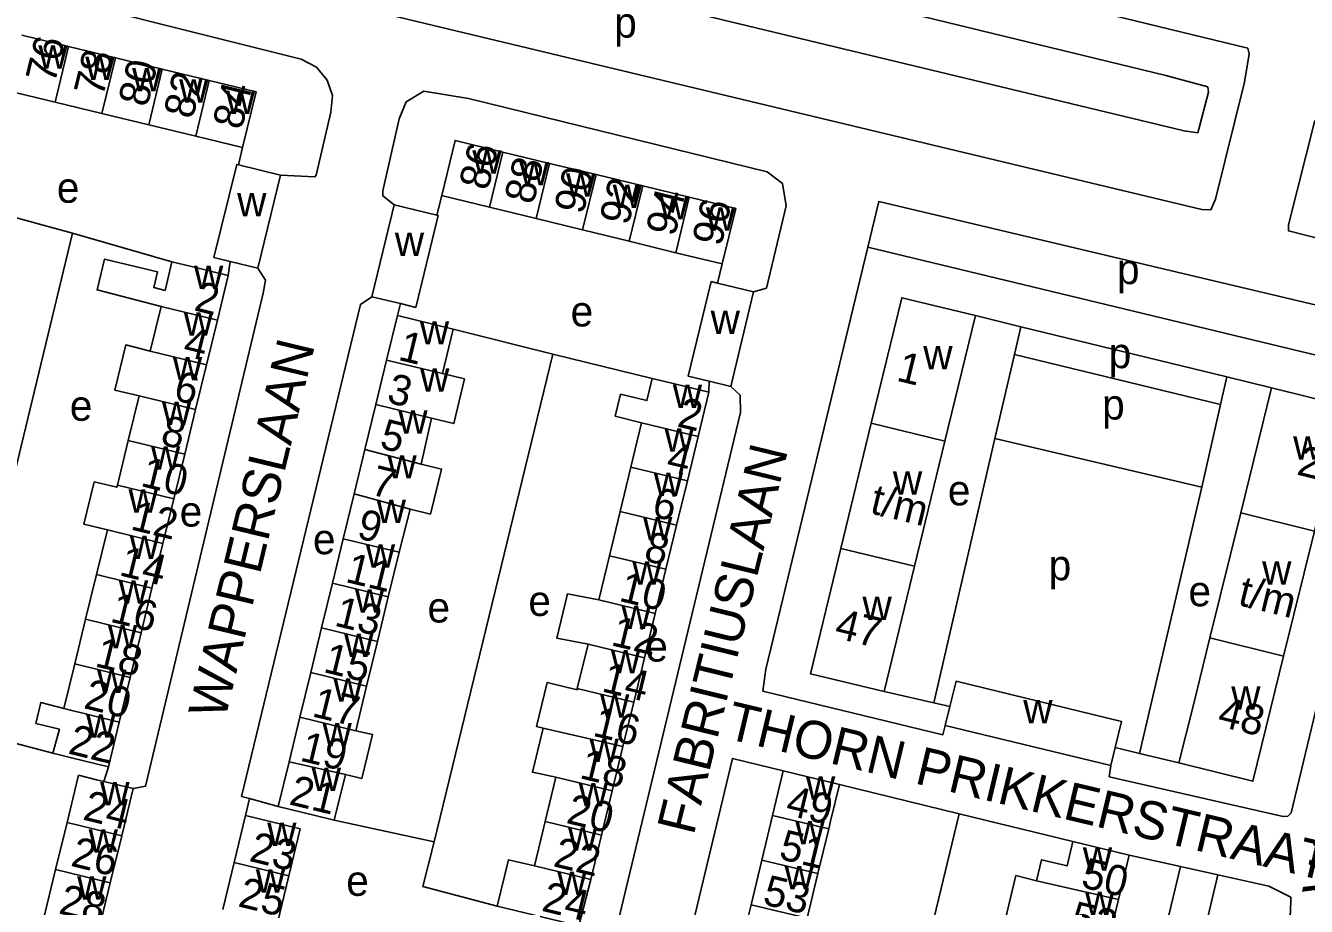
# Model space of a CAD drawing. Extents: x 162804 to 165059, y 381530 to 382901.
# Drawn here: x 163597.8 to 163766.6, y 382106.1 to 382222.2 of the extents above; entities that cross this region are included whole.
import ezdxf

# ---------------------------------------------------------------- set-up
doc = ezdxf.new("R2010")
doc.units = 0
for name, color, linetype in [('BLT_Basislijn', 7, 'Continuous'), ('BLT_Bebouwing', 7, 'Continuous'), ('BLT_Centroide', 7, 'Continuous'), ('BLT_Huisnummer', 7, 'Continuous'), ('BLT_Huisnummer_ tussenligend', 7, 'Continuous'), ('BLT_Huisnummer_reeks', 7, 'Continuous'), ('BLT_Onderverdeling_panden', 7, 'Continuous'), ('BLT_Straatnaam', 7, 'Continuous')]:
    doc.layers.add(name, color=color, linetype=linetype)

msp = doc.modelspace()

# ---------------------------------------------------------------- linework, layer by layer
at = {"layer": 'BLT_Basislijn'}
for p, q in [((163625.89, 382203.82), (163626.42, 382206.12)), ((163652.03, 382197.22), (163652.67, 382199.79)), ((163591.17, 382198.33), (163604.02, 382194.84)), ((163604.02, 382194.84), (163617.1, 382191.06)), ((163708.82, 382193), (163776.35, 382176.69)), ((163624.78, 382191.1), (163624.54, 382189.24)), ((163689.02, 382188.24), (163689.64, 382190.77)), ((163646.82, 382183.99), (163647.21, 382185.55)), ((163729, 382182.49), (163722.99, 382183.96)), ((163667.3, 382178.87), (163654.17, 382182.2)), ((163729, 382182.49), (163728.13, 382178.85)), ((163756.13, 382175.88), (163729, 382182.49)), ((163667.3, 382178.87), (163651.65, 382114.63)), ((163680.41, 382175.69), (163667.3, 382178.87)), ((163725.53, 382167.77), (163728.13, 382178.85)), ((163728.13, 382178.85), (163755.31, 382172.24)), ((163687.85, 382173.89), (163687.91, 382175.32)), ((163755.31, 382172.24), (163756.13, 382175.88)), ((163762.03, 382174.44), (163756.13, 382175.88)), ((163752.81, 382161.36), (163755.31, 382172.24)), ((163725.53, 382167.77), (163717.53, 382132.92)), ((163725.53, 382167.77), (163752.81, 382161.36)), ((163752.81, 382161.36), (163744.6, 382126.26)), ((163717.53, 382132.92), (163710.96, 382134.41)), ((163719.62, 382132.44), (163717.53, 382132.92)), ((163601.42, 382126.29), (163588.25, 382129.72)), ((163744.6, 382126.26), (163741.39, 382127.03)), ((163749.81, 382125.01), (163744.6, 382126.26)), ((163608.13, 382122.58), (163608.74, 382124.5)), ((163705.08, 382122.19), (163720.87, 382118.32)), ((163626.82, 382118.07), (163627.33, 382120.31)), ((163631.13, 382119.27), (163627.33, 382120.31)), ((163720.87, 382118.32), (163735.85, 382114.65)), ((163651.65, 382114.63), (163638.48, 382117.49)), ((163743.26, 382112.86), (163750.03, 382111.37)), ((163750.03, 382111.37), (163754.92, 382110.28)), ((163754.92, 382110.28), (163732.81, 382015.31))]:
    msp.add_line(p, q, dxfattribs=at)
for points in [[(163535.81, 382273.16), (163541.5, 382271.99), (163758.91, 382219.21), (163759.07, 382218.46), (163758.45, 382214.75), (163754.63, 382199.3), (163754.03, 382197.92), (163752.81, 382197.95), (163531.23, 382251.04)], [(163534.57, 382267.49), (163748.1, 382215.63), (163753.62, 382214.11), (163753.7, 382213.43), (163752.3, 382208.06), (163750.49, 382208.3), (163532.9, 382260.7)], [(163584.4, 382214.48), (163582.73, 382215.55), (163583.19, 382218.74), (163585.18, 382225.87), (163587.83, 382228.45), (163591.81, 382228.37), (163634.14, 382217.78), (163636.14, 382216.71), (163637.58, 382214.99), (163638.26, 382212.97), (163638.03, 382210.78), (163636.11, 382202.48), (163635.95, 382202.25), (163631.41, 382202.47)], [(163646.4, 382198.58), (163644.88, 382199.75), (163644.88, 382200.39), (163647.04, 382209.91), (163647.99, 382212.14), (163650.32, 382213.56), (163656.2, 382212.59), (163695.54, 382202.93), (163697.55, 382201.39), (163698.04, 382198.44), (163695.45, 382187.58), (163693.75, 382187.1)], [(163767.73, 382209.7), (163764.26, 382195.93), (163764.26, 382195.13), (163784.61, 382189.94)], [(163708.82, 382193), (163710.26, 382198.99), (163771.27, 382184.56), (163774.28, 382183.7), (163774.6, 382183.28), (163776.2, 382178.16), (163776.35, 382176.69)], [(163604.02, 382194.84), (163588.41, 382130.31), (163588.25, 382129.72)], [(163719.02, 382129.96), (163718.7, 382128.72), (163694.97, 382134.49), (163695.39, 382137.36), (163708.82, 382193)], [(163612.01, 382121.63), (163613.61, 382121.94), (163614.17, 382124.15), (163629.13, 382186.91), (163629.46, 382188.63), (163628.42, 382190.21)], [(163627.33, 382120.31), (163626.28, 382120.6), (163641.94, 382185.45), (163643.46, 382186.46)], [(163740.82, 382124.67), (163740.64, 382123.19), (163763.56, 382117.95), (163764.15, 382117.99), (163764.61, 382118.42), (163777.72, 382173.12), (163776.35, 382176.69)], [(163675.58, 382102.71), (163675.78, 382103.6), (163692.02, 382171.18), (163691.99, 382173.46), (163690.74, 382174.64)], [(163697.68, 382123.98), (163690.97, 382125.61), (163677.03, 382067.34), (163676.86, 382066.6)], [(163720.87, 382118.32), (163706.89, 382060.39), (163706.7, 382059.59)], [(163651.65, 382114.63), (163650.16, 382108.74), (163659.98, 382106.16)], [(163750.03, 382111.37), (163736.1, 382053.27), (163735.94, 382052.58)], [(163754.92, 382110.28), (163761.65, 382108.79), (163764.56, 382107.32), (163764.5, 382105.25), (163740.03, 382022.17), (163738.54, 382016.32), (163737.66, 382015.32), (163736.41, 382014.92), (163732.81, 382015.31)]]:
    msp.add_lwpolyline(points, dxfattribs=at)
at = {"layer": 'BLT_Bebouwing'}
for p, q in [((163597.31, 382220.93), (163603.48, 382219.44)), ((163603.48, 382219.44), (163609.66, 382217.95)), ((163609.66, 382217.95), (163615.84, 382216.46)), ((163615.84, 382216.46), (163622.02, 382214.96)), ((163601.71, 382212.09), (163595.53, 382213.58)), ((163607.89, 382210.6), (163601.71, 382212.09)), ((163614.06, 382209.1), (163607.89, 382210.6)), ((163620.24, 382207.61), (163614.06, 382209.1)), ((163626.42, 382206.12), (163620.24, 382207.61)), ((163660.72, 382205.52), (163666.87, 382204.03)), ((163666.87, 382204.03), (163673.01, 382202.55)), ((163625.89, 382203.82), (163631.41, 382202.47)), ((163631.41, 382202.47), (163628.42, 382190.21)), ((163673.01, 382202.55), (163679.15, 382201.06)), ((163679.15, 382201.06), (163685.29, 382199.57)), ((163646.4, 382198.58), (163643.46, 382186.46)), ((163652.03, 382197.22), (163646.4, 382198.58)), ((163665.09, 382196.76), (163658.95, 382198.25)), ((163671.23, 382195.26), (163665.09, 382196.76)), ((163677.37, 382193.76), (163671.23, 382195.26)), ((163683.51, 382192.26), (163677.37, 382193.76)), ((163689.64, 382190.77), (163683.51, 382192.26)), ((163628.42, 382190.21), (163624.78, 382191.1)), ((163624.54, 382189.24), (163623.1, 382183.36)), ((163693.75, 382187.1), (163689.02, 382188.24)), ((163690.74, 382174.64), (163693.75, 382187.1)), ((163643.46, 382186.46), (163647.21, 382185.55)), ((163615.67, 382185.17), (163614.23, 382179.29)), ((163645.4, 382178.11), (163646.82, 382183.99)), ((163722.99, 382183.96), (163718.98, 382167.44)), ((163623.1, 382183.36), (163621.67, 382177.47)), ((163654.17, 382182.2), (163652.75, 382176.33)), ((163621.67, 382177.47), (163620.23, 382171.59)), ((163643.97, 382172.23), (163645.4, 382178.11)), ((163687.91, 382175.32), (163690.74, 382174.64)), ((163687.85, 382173.89), (163686.44, 382168.05)), ((163762.03, 382174.44), (163757.96, 382157.96)), ((163612.79, 382173.4), (163611.35, 382167.52)), ((163642.54, 382166.34), (163643.97, 382172.23)), ((163620.23, 382171.59), (163618.79, 382165.7)), ((163651.32, 382170.44), (163649.95, 382164.4)), ((163679, 382169.85), (163677.59, 382164.01)), ((163705.26, 382153.28), (163709.27, 382169.8)), ((163611.35, 382167.52), (163609.92, 382161.63)), ((163686.44, 382168.05), (163685.03, 382162.21)), ((163718.98, 382167.44), (163714.97, 382150.93)), ((163618.79, 382165.7), (163617.36, 382159.82)), ((163641.12, 382160.46), (163642.54, 382166.34)), ((163677.59, 382164.01), (163676.18, 382158.17)), ((163685.03, 382162.21), (163683.62, 382156.37)), ((163639.69, 382154.57), (163641.12, 382160.46)), ((163617.36, 382159.82), (163615.92, 382153.93)), ((163648.51, 382158.47), (163647.04, 382152.79)), ((163676.18, 382158.17), (163674.76, 382152.33)), ((163757.96, 382157.96), (163753.89, 382141.48)), ((163608.61, 382155.72), (163607.17, 382149.83)), ((163683.62, 382156.37), (163682.2, 382150.53)), ((163763.61, 382139.08), (163767.68, 382155.56)), ((163615.92, 382153.93), (163614.48, 382148.05)), ((163638.26, 382148.69), (163639.69, 382154.57)), ((163647.04, 382152.79), (163645.61, 382146.91)), ((163674.76, 382152.33), (163673.35, 382146.49)), ((163682.2, 382150.53), (163680.79, 382144.69)), ((163714.97, 382150.93), (163710.96, 382134.41)), ((163607.17, 382149.83), (163605.73, 382143.95)), ((163636.84, 382142.81), (163638.26, 382148.69)), ((163614.48, 382148.05), (163613.05, 382142.16)), ((163645.61, 382146.91), (163644.19, 382141.02)), ((163605.73, 382143.95), (163604.3, 382138.06)), ((163680.79, 382144.69), (163679.38, 382138.85)), ((163613.05, 382142.16), (163611.61, 382136.28)), ((163635.41, 382136.92), (163636.84, 382142.81)), ((163644.19, 382141.02), (163642.76, 382135.14)), ((163671.94, 382140.65), (163670.53, 382134.81)), ((163679.38, 382138.85), (163677.96, 382133.01)), ((163604.3, 382138.06), (163602.86, 382132.18)), ((163633.98, 382131.04), (163635.41, 382136.92)), ((163611.61, 382136.28), (163610.17, 382130.39)), ((163642.76, 382135.14), (163641.34, 382129.26)), ((163677.96, 382133.01), (163676.55, 382127.17)), ((163719.02, 382129.96), (163719.62, 382132.44)), ((163610.17, 382130.39), (163608.74, 382124.5)), ((163632.56, 382125.15), (163633.98, 382131.04)), ((163740.82, 382124.67), (163719.02, 382129.96)), ((163676.55, 382127.17), (163675.14, 382121.33)), ((163741.39, 382127.03), (163740.82, 382124.67)), ((163631.13, 382119.27), (163632.56, 382125.15)), ((163640, 382123.47), (163638.48, 382117.49)), ((163667.7, 382123.13), (163666.29, 382117.29)), ((163696.26, 382118.1), (163697.68, 382123.98)), ((163697.68, 382123.98), (163705.08, 382122.19)), ((163608.13, 382122.58), (163612.01, 382121.63)), ((163612.01, 382121.63), (163610.49, 382115.42)), ((163675.14, 382121.33), (163673.73, 382115.49)), ((163626.82, 382118.07), (163625.32, 382111.88)), ((163694.84, 382112.22), (163696.26, 382118.1)), ((163601.77, 382110.97), (163603.29, 382117.18)), ((163666.29, 382117.29), (163664.88, 382111.45)), ((163703.66, 382116.32), (163702.24, 382110.43)), ((163610.49, 382115.42), (163608.98, 382109.21)), ((163673.73, 382115.49), (163672.31, 382109.65)), ((163743.26, 382112.86), (163735.85, 382114.65)), ((163741.85, 382107.01), (163743.26, 382112.86)), ((163625.32, 382111.88), (163623.82, 382105.69)), ((163693.42, 382106.33), (163694.84, 382112.22)), ((163600.25, 382104.77), (163601.77, 382110.97)), ((163631.01, 382103.94), (163632.51, 382110.14)), ((163672.31, 382109.65), (163670.72, 382103.55)), ((163702.24, 382110.43), (163700.82, 382104.55)), ((163608.98, 382109.21), (163607.46, 382103.01)), ((163659.98, 382106.16), (163670.72, 382103.55)), ((163692.01, 382100.45), (163693.42, 382106.33)), ((163740.44, 382101.14), (163741.85, 382107.01))]:
    msp.add_line(p, q, dxfattribs=at)
for points in [[(163622.02, 382214.96), (163628.2, 382213.47), (163626.42, 382206.12)], [(163652.67, 382199.79), (163654.43, 382207.05), (163660.72, 382205.52)], [(163624.78, 382191.1), (163622.65, 382191.62), (163625.64, 382203.88), (163625.89, 382203.82)], [(163658.95, 382198.25), (163652.81, 382199.75), (163652.67, 382199.79)], [(163685.29, 382199.57), (163691.42, 382198.09), (163689.64, 382190.77)], [(163647.21, 382185.55), (163649.24, 382185.05), (163652.18, 382197.18), (163652.03, 382197.22)], [(163617.1, 382191.06), (163616.72, 382189.35), (163616.22, 382187.28), (163614.72, 382187.65), (163615.22, 382189.72), (163608.24, 382191.42), (163607.25, 382187.36), (163615.67, 382185.17)], [(163624.54, 382189.24), (163619.68, 382190.43), (163617.1, 382191.06)], [(163689.02, 382188.24), (163688.15, 382188.45), (163685.13, 382176), (163687.91, 382175.32)], [(163709.27, 382169.8), (163713.28, 382186.31), (163722.99, 382183.96)], [(163646.82, 382183.99), (163651.68, 382182.81), (163654.17, 382182.2)], [(163614.23, 382179.29), (163611.02, 382180.11), (163609.57, 382174.15), (163612.79, 382173.4)], [(163652.75, 382176.33), (163655.66, 382175.62), (163654.24, 382169.74), (163651.32, 382170.44)], [(163680.41, 382175.69), (163679.71, 382172.76), (163676.23, 382173.6), (163675.54, 382170.73), (163679, 382169.85)], [(163687.85, 382173.89), (163682.99, 382175.06), (163680.41, 382175.69)], [(163767.68, 382155.56), (163771.75, 382172.04), (163762.03, 382174.44)], [(163649.95, 382164.4), (163652.65, 382163.74), (163651.2, 382157.81), (163648.51, 382158.47)], [(163609.92, 382161.63), (163609.84, 382161.34), (163606.87, 382162.06), (163605.51, 382156.47), (163608.61, 382155.72)], [(163710.96, 382134.41), (163701.25, 382136.77), (163705.26, 382153.28)], [(163673.35, 382146.49), (163669.22, 382147.28), (163667.81, 382141.47), (163671.94, 382140.65)], [(163753.89, 382141.48), (163751.67, 382132.51), (163749.81, 382125.01)], [(163749.81, 382125.01), (163759.54, 382122.6), (163763.61, 382139.08)], [(163670.53, 382134.81), (163670.49, 382134.67), (163666.56, 382135.62), (163665.16, 382129.81), (163666.03, 382129.6)], [(163719.62, 382132.44), (163720.44, 382135.79), (163742.23, 382130.49), (163741.39, 382127.03)], [(163602.86, 382132.18), (163599.85, 382132.98), (163599.18, 382130.23), (163602.28, 382129.48), (163601.42, 382126.29)], [(163641.34, 382129.26), (163643.54, 382128.78), (163642.13, 382122.95), (163640, 382123.47)], [(163666.03, 382129.6), (163664.62, 382123.78), (163667.7, 382123.13)], [(163601.42, 382126.29), (163603.88, 382125.69), (163608.74, 382124.5)], [(163603.29, 382117.18), (163604.8, 382123.39), (163607.15, 382122.81), (163608.13, 382122.58)], [(163705.08, 382122.19), (163703.9, 382117.33), (163703.66, 382116.32)], [(163632.51, 382110.14), (163634.01, 382116.33), (163631.68, 382116.9), (163626.82, 382118.07)], [(163638.48, 382117.49), (163635.99, 382118.09), (163631.13, 382119.27)], [(163735.85, 382114.65), (163735.07, 382111.44), (163731.72, 382112.25), (163731.05, 382109.47)], [(163664.88, 382111.45), (163661.46, 382112.24), (163659.98, 382106.16)], [(163731.05, 382109.47), (163728.32, 382110.17), (163726.92, 382104.28), (163729.65, 382103.63), (163733, 382102.83)]]:
    msp.add_lwpolyline(points, dxfattribs=at)
at = {"layer": 'BLT_Onderverdeling_panden'}
for p, q in [((163601.71, 382212.09), (163603.48, 382219.44)), ((163607.89, 382210.6), (163609.66, 382217.95)), ((163614.06, 382209.1), (163615.84, 382216.46)), ((163620.24, 382207.61), (163622.02, 382214.96)), ((163658.95, 382198.25), (163660.72, 382205.52)), ((163665.09, 382196.76), (163666.87, 382204.03)), ((163671.23, 382195.26), (163673.01, 382202.55)), ((163677.37, 382193.76), (163679.15, 382201.06)), ((163683.51, 382192.26), (163685.29, 382199.57)), ((163615.67, 382185.17), (163623.1, 382183.36)), ((163614.23, 382179.29), (163621.67, 382177.47)), ((163652.75, 382176.33), (163645.4, 382178.11)), ((163612.79, 382173.4), (163620.23, 382171.59)), ((163651.32, 382170.44), (163643.97, 382172.23)), ((163679, 382169.85), (163686.44, 382168.05)), ((163718.98, 382167.44), (163709.27, 382169.8)), ((163611.35, 382167.52), (163618.79, 382165.7)), ((163649.95, 382164.4), (163642.54, 382166.34)), ((163677.59, 382164.01), (163685.03, 382162.21)), ((163609.92, 382161.63), (163617.36, 382159.82)), ((163648.51, 382158.47), (163641.12, 382160.46)), ((163676.18, 382158.17), (163683.62, 382156.37)), ((163767.68, 382155.56), (163757.96, 382157.96)), ((163608.61, 382155.72), (163615.92, 382153.93)), ((163647.04, 382152.79), (163639.69, 382154.57)), ((163714.97, 382150.93), (163705.26, 382153.28)), ((163674.76, 382152.33), (163682.2, 382150.53)), ((163607.17, 382149.83), (163614.48, 382148.05)), ((163645.61, 382146.91), (163638.26, 382148.69)), ((163673.35, 382146.49), (163680.79, 382144.69)), ((163605.73, 382143.95), (163613.05, 382142.16)), ((163644.19, 382141.02), (163636.84, 382142.81)), ((163763.61, 382139.08), (163753.89, 382141.48)), ((163671.94, 382140.65), (163679.38, 382138.85)), ((163604.3, 382138.06), (163611.61, 382136.28)), ((163642.76, 382135.14), (163635.41, 382136.92)), ((163670.53, 382134.81), (163677.96, 382133.01)), ((163602.86, 382132.18), (163610.17, 382130.39)), ((163641.34, 382129.26), (163633.98, 382131.04)), ((163666.03, 382129.6), (163676.55, 382127.17)), ((163640, 382123.47), (163632.56, 382125.15)), ((163667.7, 382123.13), (163675.14, 382121.33)), ((163703.66, 382116.32), (163696.26, 382118.1)), ((163610.49, 382115.42), (163603.29, 382117.18)), ((163666.29, 382117.29), (163673.73, 382115.49)), ((163632.51, 382110.14), (163625.32, 382111.88)), ((163664.88, 382111.45), (163672.31, 382109.65)), ((163702.24, 382110.43), (163694.84, 382112.22)), ((163608.98, 382109.21), (163601.77, 382110.97)), ((163741.85, 382107.01), (163731.05, 382109.47)), ((163700.82, 382104.55), (163693.42, 382106.33))]:
    msp.add_line(p, q, dxfattribs=at)

# ---------------------------------------------------------------- texts
at = {"layer": 'BLT_Centroide'}
for s, p in [('p', (163675.39, 382220.6)), ('w', (163599.5, 382216.52)), ('w', (163605.69, 382215.02)), ('w', (163611.86, 382213.52)), ('w', (163618.05, 382212.05)), ('w', (163624.22, 382210.55)), ('w', (163656.7, 382202.66)), ('w', (163662.91, 382201.14)), ('w', (163669.05, 382199.64)), ('e', (163601.94, 382198.84)), ('w', (163675.19, 382198.16)), ('w', (163625.7, 382197.05)), ('w', (163681.33, 382196.66)), ('w', (163687.47, 382195.17)), ('w', (163646.48, 382191.83)), ('w', (163620.01, 382187.47)), ('p', (163741.65, 382188.12)), ('e', (163669.65, 382182.54)), ('w', (163618.67, 382181.33)), ('w', (163688.1, 382181.55)), ('w', (163649.78, 382180.16)), ('w', (163716.12, 382176.88)), ('p', (163740.56, 382177.04)), ('w', (163617.23, 382175.43)), ('w', (163649.81, 382173.94)), ('w', (163683.11, 382171.81)), ('e', (163603.65, 382170.11)), ('w', (163615.79, 382169.55)), ('p', (163739.69, 382170.27)), ('w', (163646.94, 382168.41)), ('w', (163682.02, 382166.03)), ('w', (163764.86, 382165)), ('w', (163614.35, 382163.68)), ('w', (163645.5, 382162.5)), ('w', (163712.12, 382160.36)), ('w', (163680.6, 382160.19)), ('e', (163719.36, 382158.96)), ('w', (163611.39, 382157.99)), ('e', (163618.13, 382156.16)), ('w', (163644.08, 382156.62)), ('w', (163679.19, 382154.35)), ('w', (163611.55, 382151.9)), ('e', (163635.69, 382152.52)), ('w', (163642.66, 382150.75)), ('w', (163677.78, 382148.5)), ('p', (163732.65, 382149.09)), ('w', (163760.78, 382148.52)), ('w', (163610.11, 382145.99)), ('e', (163751.07, 382145.66)), ('w', (163641.22, 382144.84)), ('e', (163650.79, 382143.52)), ('e', (163664.08, 382144.38)), ('w', (163708.11, 382143.84)), ('w', (163676.36, 382142.66)), ('w', (163608.67, 382140.12)), ('w', (163639.8, 382138.97)), ('e', (163679.5, 382138.37)), ('w', (163674.96, 382136.81)), ('w', (163607.24, 382134.24)), ('w', (163638.38, 382133.09)), ('w', (163756.7, 382132.05)), ('w', (163673.53, 382131)), ('w', (163729.3, 382130.22)), ('w', (163605.8, 382128.33)), ('w', (163636.95, 382127.22)), ('w', (163672.13, 382125.16)), ('w', (163635.52, 382121.31)), ('w', (163700.66, 382120.16)), ('w', (163607.65, 382119.41)), ('w', (163670.71, 382119.31)), ('w', (163606.13, 382113.19)), ('w', (163629.66, 382114.09)), ('w', (163669.3, 382113.47)), ('w', (163699.26, 382114.28)), ('w', (163737.15, 382110.81)), ('w', (163697.84, 382108.38)), ('w', (163604.62, 382107)), ('w', (163628.16, 382107.91)), ('e', (163640.08, 382107.5)), ('w', (163667.89, 382107.63)), ('w', (163737.44, 382104.97))]:
    msp.add_text(s, height=4, dxfattribs=at).set_placement(p)
at = {"layer": 'BLT_Huisnummer'}
for s, rotation, p in [('78', 76.4156, (163608.02, 382212.66)), ('84', 76.4082, (163626.3, 382208.33)), ('86', 76.2871, (163658.76, 382200.33)), ('90', 76.2858, (163671.3, 382197.19)), ('96', 76.377, (163689.48, 382192.97)), ('2', 346.2776, (163619.88, 382184.69)), ('1', 346.3732, (163646.78, 382178.16)), ('6', 346.2776, (163617.17, 382172.88)), ('2', 346.3995, (163683.55, 382169.38)), ('5', 346.3732, (163644.34, 382166.53)), ('10', 346.2831, (163612.84, 382161.53)), ('6', 346.405, (163680.2, 382157.55)), ('9', 346.3714, (163641.33, 382154.67)), ('14', 346.2831, (163610.02, 382149.77)), ('10', 346.405, (163675.88, 382146.4)), ('13', 346.3697, (163638.38, 382143.13)), ('18', 346.2831, (163606.82, 382137.77)), ('14', 346.4067, (163673.61, 382134.47)), ('17', 346.3697, (163635.43, 382131.18)), ('22', 346.2778, (163603.29, 382126.28)), ('18', 346.3977, (163670.68, 382123.04)), ('21', 346.3862, (163632.41, 382119.58)), ('24', 346.2839, (163605.22, 382117.58)), ('49', 346.449, (163697.83, 382118.22)), ('23', 346.3675, (163627.15, 382112.12)), ('50', 346.45, (163736.75, 382108.68)), ('53', 346.4455, (163694.82, 382106.42)), ('24', 346.3946, (163665.68, 382105.56))]:
    msp.add_text(s, height=4, rotation=rotation, dxfattribs=at).set_placement(p)
at = {"layer": 'BLT_Huisnummer_ tussenligend'}
for s, rotation, p in [('76', 76.4156, (163601.66, 382214.42)), ('80', 76.4156, (163613.86, 382211.32)), ('82', 76.4156, (163619.84, 382209.74)), ('88', 76.2871, (163664.73, 382198.48)), ('92', 76.2858, (163677.28, 382195.74)), ('94', 76.2858, (163683.38, 382194.27)), ('4', 346.2776, (163618.41, 382178.71)), ('3', 346.3732, (163645.28, 382172.55)), ('8', 346.2776, (163615.45, 382167.03)), ('4', 346.3995, (163682.08, 382163.54)), ('7', 346.3732, (163643.13, 382160.42)), ('12', 346.2831, (163611.52, 382155.81)), ('8', 346.405, (163679.15, 382151.71)), ('11', 346.3714, (163639.84, 382148.89)), ('16', 346.2831, (163608.83, 382143.65)), ('12', 346.405, (163674.83, 382140.55)), ('15', 346.3697, (163636.92, 382137.02)), ('20', 346.2831, (163605.34, 382132.26)), ('16', 346.4067, (163672.42, 382128.62)), ('19', 346.3697, (163633.84, 382125.34)), ('20', 346.3977, (163668.94, 382117.13)), ('51', 346.449, (163696.95, 382112.4)), ('26', 346.2839, (163603.63, 382111.47)), ('22', 346.3977, (163667.22, 382111.42)), ('25', 346.3675, (163625.68, 382106.14)), ('28', 346.2839, (163602.04, 382105.22)), ('52', 346.45, (163735.3, 382102.96))]:
    msp.add_text(s, height=4, rotation=rotation, dxfattribs=at).set_placement(p)
at = {"layer": 'BLT_Huisnummer_reeks'}
for s, rotation, p in [('1', 346.3475, (163712.46, 382175.42)), ('2', 346.115, (163765.2, 382163.05)), ('t/m', 346.3531, (163708.96, 382157.95)), ('t/m', 346.1191, (163757.45, 382145.86)), ('47', 346.3531, (163704.27, 382141.54)), ('48', 346.1247, (163754.73, 382129.93))]:
    msp.add_text(s, height=4, rotation=rotation, dxfattribs=at).set_placement(p)
at = {"layer": 'BLT_Straatnaam'}
for s, height, rotation, p in [('WAPPERSLAAN', 5, 76.5115, (163624.1, 382130.59)), ('VAN RENESSEWEG', 5, 76.4414, (163770.87, 382106.84)), ('FABRITIUSLAAN', 5, 76.2295, (163685.85, 382115.36)), ('THORN PRIKKERSTRAAT', 4.9999, 346.6028, (163689.92, 382128.29))]:
    msp.add_text(s, height=height, rotation=rotation, dxfattribs=at).set_placement(p)

doc.saveas('drawing.dxf')
